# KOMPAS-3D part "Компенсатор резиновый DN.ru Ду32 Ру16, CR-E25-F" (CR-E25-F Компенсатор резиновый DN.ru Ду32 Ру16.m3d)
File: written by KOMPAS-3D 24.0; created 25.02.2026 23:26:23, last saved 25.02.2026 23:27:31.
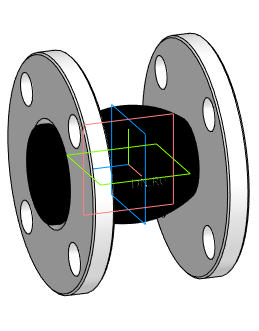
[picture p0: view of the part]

Document properties: Автор: DN.RIU; Полное имя файла: D:\PROJECT CAD\DN.RU\...178(4)(ACTUALE). CR-E25-F Компенсатор резиновый DN.ru Ру10-16\DN32_PN16\CR-E25-F Компенсатор резиновый DN.ru Ду32 Ру16.m3d

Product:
- Body: Твердое тело2  | qty 1
    Масса: 2.963372
- Part/product: Компенсатор резиновый DN.ru Ду32 Ру16  | designation CR-E25-F
    Масса: 2.94
    Раздел спецификации: Прочие изделия
    Комментарий: D140-02171
    Примечание: D140-02171
    additional columns: Типовые

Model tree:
1. Твердое тело2  (labels: Твердое тело2)

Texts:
  CR-E25-F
